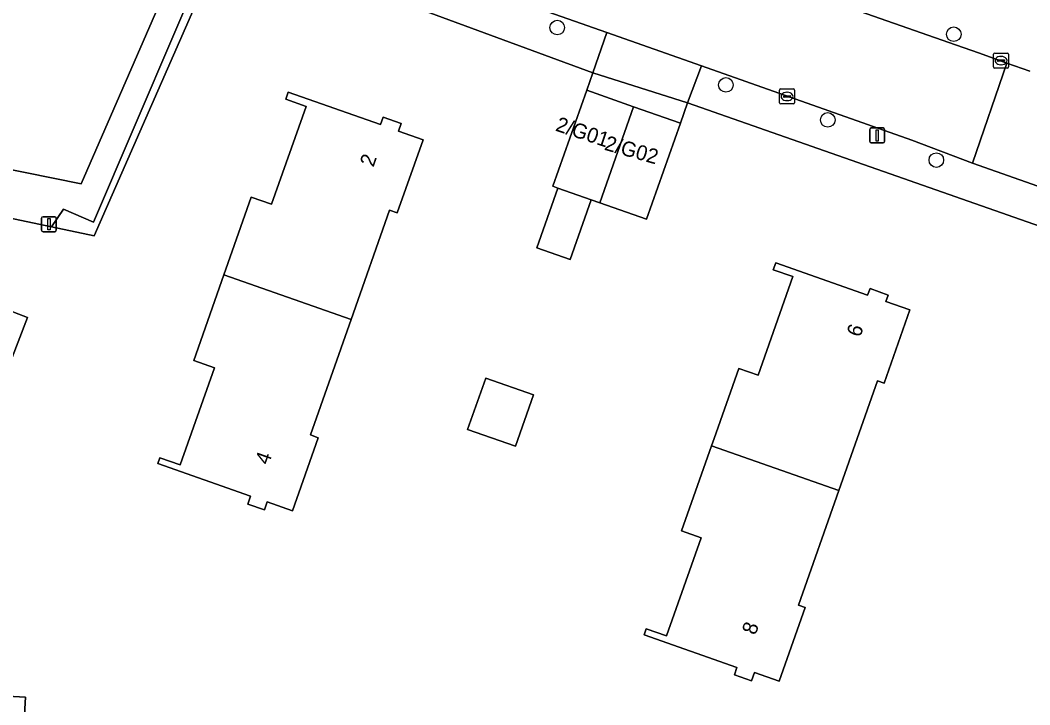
# Model space of a CAD drawing. Extents: x 163266 to 164362, y 381528 to 382286.
# Drawn here: x 163633.8 to 163701.5, y 381685.3 to 381731.2 of the extents above; entities that cross this region are included whole.
import ezdxf

# ---------------------------------------------------------------- set-up
doc = ezdxf.new("R2010")
doc.units = 0
for name, color, linetype in [('IMGEO_Boom', 7, 'Continuous'), ('IMGEO_Erf', 7, 'Continuous'), ('IMGEO_Groenvoorziening', 7, 'Continuous'), ('IMGEO_Kolk', 7, 'Continuous'), ('IMGEO_Lichtmast', 7, 'Continuous'), ('IMGEO_Pand', 7, 'Continuous'), ('IMGEO_Pand_nummerreeks', 7, 'Continuous'), ('IMGEO_Rijbaan_lokaal_open', 7, 'Continuous'), ('IMGEO_Voetpad_open', 7, 'Continuous')]:
    doc.layers.add(name, color=color, linetype=linetype)

msp = doc.modelspace()

# ---------------------------------------------------------------- linework, layer by layer
at = {"layer": 'IMGEO_Boom'}
for centre in [(163669.794, 381730.731), (163696.394, 381730.281), (163681.104, 381726.885), (163687.938, 381724.532), (163695.227, 381721.833)]:
    msp.add_circle(centre, 0.489, dxfattribs=at)
at = {"layer": 'IMGEO_Erf'}
msp.add_lwpolyline([(163745.303, 381694.051), (163749.229, 381692.724), (163751.277, 381698.534), (163751.759, 381699.934), (163743.762, 381702.736), (163737.338, 381704.902), (163711.131, 381714.194), (163704.828, 381716.464), (163678.538, 381725.673), (163678.063, 381724.312), (163675.791, 381717.865), (163672.646, 381718.973), (163672.074, 381719.175), (163670.661, 381715.164), (163668.428, 381715.95), (163669.842, 381719.961), (163669.501, 381720.081), (163671.774, 381726.529), (163672.171, 381727.69), (163647.526, 381736.802), (163638.731, 381716.751), (163635.855, 381717.357), (163618.556, 381721)], dxfattribs=at)
for points in [[(163672.171, 381727.69), (163671.774, 381726.529), (163674.918, 381725.42), (163678.063, 381724.312), (163678.538, 381725.673)], [(163649.037, 381698.745), (163649.224, 381699.275), (163642.995, 381701.47), (163643.132, 381701.857), (163644.501, 381701.374), (163646.796, 381707.886), (163645.403, 381708.377), (163647.43, 381714.128), (163649.27, 381719.35), (163650.632, 381718.87), (163652.946, 381725.436), (163651.578, 381725.918), (163651.747, 381726.398), (163657.927, 381724.22), (163658.106, 381724.727), (163659.331, 381724.295), (163659.149, 381723.779), (163660.793, 381723.2), (163659.061, 381718.285), (163658.546, 381718.466), (163655.962, 381711.134), (163653.232, 381703.385), (163653.762, 381703.198), (163652.034, 381698.296), (163650.342, 381698.892), (163650.152, 381698.352)], [(163681.848, 381687.774), (163675.623, 381689.968), (163675.769, 381690.381), (163677.132, 381689.9), (163679.45, 381696.479), (163678.139, 381696.942), (163680.149, 381702.647), (163680.322, 381703.137), (163681.984, 381707.852), (163683.267, 381707.4), (163685.597, 381714.012), (163684.288, 381714.473), (163684.449, 381714.931), (163690.617, 381712.758), (163690.775, 381713.206), (163691.99, 381712.777), (163691.838, 381712.345), (163693.449, 381711.778), (163691.715, 381706.856), (163691.274, 381707.011), (163688.681, 381699.654), (163685.969, 381691.958), (163686.429, 381691.796), (163684.688, 381686.856), (163683.016, 381687.445), (163682.815, 381686.875), (163681.673, 381687.277)], [(163625.049, 381706.105), (163627.966, 381713.682), (163634.25, 381711.263), (163631.333, 381703.686)], [(163663.783, 381703.753), (163664.997, 381707.199), (163668.206, 381706.074), (163666.992, 381702.628)], [(163630.045, 381672.483), (163622.26, 381672.933), (163622.545, 381677.925), (163622.841, 381683.109), (163623.419, 381683.076), (163623.607, 381686.383), (163628.458, 381686.107), (163634.117, 381685.785), (163633.89, 381681.792), (163633.729, 381678.958), (163630.424, 381679.148), (163630.301, 381676.99)]]:
    msp.add_lwpolyline(points, close=True, dxfattribs=at)
at = {"layer": 'IMGEO_Groenvoorziening'}
msp.add_lwpolyline([(163631.124, 381724.791), (163632.2, 381721.39), (163637.847, 381720.23), (163644.208, 381734.86)], dxfattribs=at)
at = {"layer": 'IMGEO_Kolk'}
for p, q in [((163699.065, 381728.087), (163699.065, 381728.939)), ((163699.14, 381729.013), (163699.992, 381729.013)), ((163699.367, 381728.556), (163699.765, 381728.556)), ((163699.553, 381728.793), (163699.578, 381728.793)), ((163700.066, 381728.939), (163700.066, 381728.087)), ((163699.992, 381728.013), (163699.14, 381728.013)), ((163699.324, 381728.507), (163699.324, 381728.519)), ((163699.762, 381728.47), (163699.364, 381728.47)), ((163699.576, 381728.233), (163699.551, 381728.233)), ((163699.808, 381728.519), (163699.808, 381728.507)), ((163684.71, 381725.682), (163684.71, 381726.534)), ((163684.785, 381726.608), (163685.637, 381726.608)), ((163685.711, 381726.534), (163685.711, 381725.682)), ((163684.969, 381726.102), (163684.969, 381726.114)), ((163685.407, 381726.065), (163685.009, 381726.065)), ((163685.012, 381726.151), (163685.41, 381726.151)), ((163685.221, 381725.828), (163685.196, 381725.828)), ((163685.198, 381726.388), (163685.223, 381726.388)), ((163685.453, 381726.114), (163685.453, 381726.102)), ((163685.637, 381725.608), (163684.785, 381725.608))]:
    msp.add_line(p, q, dxfattribs=at)
for points in [[(163699.065, 381728.087), (163699.065, 381728.939)], [(163699.14, 381729.013), (163699.992, 381729.013)], [(163700.066, 381728.939), (163700.066, 381728.087)], [(163699.992, 381728.013), (163699.14, 381728.013)], [(163684.71, 381725.682), (163684.71, 381726.534)], [(163684.785, 381726.608), (163685.637, 381726.608)], [(163685.711, 381726.534), (163685.711, 381725.682)], [(163685.637, 381725.608), (163684.785, 381725.608)]]:
    msp.add_lwpolyline(points, dxfattribs=at)
for centre, radius, start, end in [((163699.142, 381728.937), 0.0765, 91.55205, 178.44795), ((163699.142, 381728.937), 0.0765, 91.55205, 178.44795), ((163699.364, 381728.516), 0.0403, 85.87752, 175.75265), ((163699.769, 381728.518), 0.0386, 1.73085, 96.63898), ((163699.99, 381728.937), 0.0765, 1.55205, 88.44795), ((163699.99, 381728.937), 0.0765, 1.55205, 88.44795), ((163699.142, 381728.089), 0.0765, 181.55205, 268.44795), ((163699.142, 381728.089), 0.0765, 181.55205, 268.44795), ((163699.361, 381728.506), 0.0366, 178.93798, 274.71019), ((163699.765, 381728.513), 0.043, 264.86636, 352.45326), ((163699.99, 381728.089), 0.0765, 271.55205, 358.44795), ((163699.99, 381728.089), 0.0765, 271.55205, 358.44795), ((163684.787, 381726.532), 0.0765, 91.55205, 178.44795), ((163684.787, 381726.532), 0.0765, 91.55205, 178.44795), ((163685.635, 381726.532), 0.0765, 1.55205, 88.44795), ((163685.635, 381726.532), 0.0765, 1.55205, 88.44795), ((163685.009, 381726.111), 0.0403, 85.87752, 175.75265), ((163685.006, 381726.101), 0.0366, 178.93798, 274.71019), ((163685.41, 381726.108), 0.043, 264.86636, 352.45326), ((163685.414, 381726.113), 0.0386, 1.73085, 96.63898), ((163684.787, 381725.684), 0.0765, 181.55205, 268.44795), ((163684.787, 381725.684), 0.0765, 181.55205, 268.44795), ((163685.635, 381725.684), 0.0765, 271.55205, 358.44795), ((163685.635, 381725.684), 0.0765, 271.55205, 358.44795)]:
    msp.add_arc(centre, radius, start, end, dxfattribs=at)
for centre, major_axis, ratio, start_param, end_param in [((163699.552, 381728.513), (-0.387, 0.002), 0.722429, 4.712389, 7.853982), ((163699.577, 381728.513), (-0.39, 0.002), 0.717154, 1.570796, 4.712389), ((163685.197, 381726.108), (-0.387, 0.002), 0.722429, 4.712389, 7.853982), ((163685.222, 381726.108), (-0.39, 0.002), 0.717154, 1.570796, 4.712389)]:
    msp.add_ellipse(centre, major_axis=major_axis, ratio=ratio, start_param=start_param, end_param=end_param, dxfattribs=at)
at = {"layer": 'IMGEO_Lichtmast'}
for p, q in [((163690.761, 381723.089), (163690.761, 381723.889)), ((163690.761, 381723.889), (163690.761, 381723.089)), ((163690.861, 381723.989), (163691.651, 381723.989)), ((163691.651, 381723.989), (163690.861, 381723.989)), ((163691.751, 381723.889), (163691.751, 381723.089)), ((163691.751, 381723.089), (163691.751, 381723.889)), ((163691.651, 381722.989), (163690.861, 381722.989)), ((163690.861, 381722.989), (163691.651, 381722.989)), ((163635.196, 381717.129), (163635.196, 381717.929)), ((163635.196, 381717.929), (163635.196, 381717.129)), ((163635.296, 381718.029), (163636.086, 381718.029)), ((163636.086, 381718.029), (163635.296, 381718.029)), ((163636.186, 381717.929), (163636.186, 381717.129)), ((163636.186, 381717.129), (163636.186, 381717.929)), ((163636.086, 381717.029), (163635.296, 381717.029)), ((163635.296, 381717.029), (163636.086, 381717.029))]:
    msp.add_line(p, q, dxfattribs=at)
for points in [[(163691.181, 381723.864), (163691.331, 381723.864), (163691.331, 381723.114), (163691.181, 381723.114), (163691.181, 381723.864)], [(163635.616, 381717.904), (163635.766, 381717.904), (163635.766, 381717.154), (163635.616, 381717.154), (163635.616, 381717.904)]]:
    msp.add_lwpolyline(points, dxfattribs=at)
for centre, start, end in [((163690.861, 381723.889), 90, 180), ((163690.861, 381723.889), 90, 180), ((163691.651, 381723.889), 0, 90), ((163691.651, 381723.889), 360, 90), ((163690.861, 381723.089), 180, 270), ((163690.861, 381723.089), 180, 270), ((163691.651, 381723.089), 270, 0), ((163691.651, 381723.089), 270, 0), ((163635.296, 381717.929), 90, 180), ((163635.296, 381717.929), 90, 180), ((163636.086, 381717.929), 0, 90), ((163636.086, 381717.929), 360, 90), ((163635.296, 381717.129), 180, 270), ((163635.296, 381717.129), 180, 270), ((163636.086, 381717.129), 270, 0), ((163636.086, 381717.129), 270, 0)]:
    msp.add_arc(centre, 0.1, start, end, dxfattribs=at)
at = {"layer": 'IMGEO_Pand'}
for points in [[(163674.918, 381725.42), (163671.774, 381726.529), (163669.501, 381720.081), (163669.842, 381719.961), (163672.074, 381719.175), (163672.646, 381718.973)], [(163647.43, 381714.128), (163655.962, 381711.134), (163658.546, 381718.466), (163659.061, 381718.285), (163660.793, 381723.2), (163659.149, 381723.779), (163659.331, 381724.295), (163658.106, 381724.727), (163657.927, 381724.22), (163651.747, 381726.398), (163651.578, 381725.918), (163652.946, 381725.436), (163650.632, 381718.87), (163649.27, 381719.35)], [(163675.791, 381717.865), (163678.063, 381724.312), (163674.918, 381725.42), (163672.646, 381718.973)], [(163672.074, 381719.175), (163669.842, 381719.961), (163668.428, 381715.95), (163670.661, 381715.164)], [(163680.149, 381702.647), (163688.681, 381699.654), (163691.274, 381707.011), (163691.715, 381706.856), (163693.449, 381711.778), (163691.838, 381712.345), (163691.99, 381712.777), (163690.775, 381713.206), (163690.617, 381712.758), (163684.449, 381714.931), (163684.288, 381714.473), (163685.597, 381714.012), (163683.267, 381707.4), (163681.984, 381707.852), (163680.322, 381703.137)], [(163634.25, 381711.263), (163627.966, 381713.682), (163625.049, 381706.105), (163631.333, 381703.686)], [(163647.43, 381714.128), (163645.403, 381708.377), (163646.796, 381707.886), (163644.501, 381701.374), (163643.132, 381701.857), (163642.995, 381701.47), (163649.224, 381699.275), (163649.037, 381698.745), (163650.152, 381698.352), (163650.342, 381698.892), (163652.034, 381698.296), (163653.762, 381703.198), (163653.232, 381703.385), (163655.962, 381711.134)], [(163663.783, 381703.753), (163666.992, 381702.628), (163668.206, 381706.074), (163664.997, 381707.199)], [(163680.149, 381702.647), (163678.139, 381696.942), (163679.45, 381696.479), (163677.132, 381689.9), (163675.769, 381690.381), (163675.623, 381689.968), (163681.848, 381687.774), (163681.673, 381687.277), (163682.815, 381686.875), (163683.016, 381687.445), (163684.688, 381686.856), (163686.429, 381691.796), (163685.969, 381691.958), (163688.681, 381699.654)], [(163633.89, 381681.792), (163634.117, 381685.785), (163628.458, 381686.107), (163623.607, 381686.383), (163623.419, 381683.076), (163622.841, 381683.109), (163622.545, 381677.925), (163622.26, 381672.933), (163630.045, 381672.483), (163630.301, 381676.99), (163630.424, 381679.148), (163633.729, 381678.958)]]:
    msp.add_lwpolyline(points, close=True, dxfattribs=at)
at = {"layer": 'IMGEO_Rijbaan_lokaal_open'}
msp.add_lwpolyline([(163658.899, 381742.752), (163654.429, 381744.322), (163652.132, 381737.784), (163673.109, 381730.393), (163679.468, 381728.152), (163693.576, 381723.182), (163697.64, 381721.621), (163699.958, 381728.351), (163698.123, 381729.013), (163696.505, 381729.58)], close=True, dxfattribs=at)
msp.add_lwpolyline([(163701.495, 381727.796), (163699.958, 381728.351), (163697.64, 381721.621), (163705.584, 381718.826), (163712, 381716.568), (163727.274, 381711.194), (163729.531, 381717.818), (163728.582, 381718.152)], dxfattribs=at)
at = {"layer": 'IMGEO_Voetpad_open'}
for points in [[(163681.177, 381738.741), (163679.939, 381739.182), (163679.863, 381738.968), (163672.598, 381741.556), (163672.674, 381741.768), (163655.729, 381747.8), (163654.429, 381744.322), (163658.899, 381742.752), (163696.505, 381729.58), (163698.123, 381729.013), (163699.958, 381728.351), (163701.495, 381727.796)], [(163618.556, 381721), (163635.855, 381717.357), (163636.66, 381718.535), (163638.684, 381717.669), (163646.93, 381736.976), (163647.539, 381739.402), (163645.29, 381740.061), (163643.927, 381740.549), (163642.897, 381740.905)], [(163644.208, 381734.86), (163637.847, 381720.23), (163632.2, 381721.39), (163631.124, 381724.791)]]:
    msp.add_lwpolyline(points, dxfattribs=at)
for points in [[(163652.132, 381737.784), (163650.44, 381738.38), (163648.445, 381739.083), (163647.846, 381739.294), (163647.539, 381739.402), (163646.93, 381736.976), (163647.526, 381736.802), (163672.171, 381727.69), (163673.109, 381730.393)], [(163647.526, 381736.802), (163646.93, 381736.976), (163638.684, 381717.669), (163636.66, 381718.535), (163635.855, 381717.357), (163638.731, 381716.751)], [(163678.538, 381725.673), (163679.468, 381728.152), (163673.109, 381730.393), (163672.171, 381727.69)], [(163693.576, 381723.182), (163679.468, 381728.152), (163678.538, 381725.673), (163704.828, 381716.464), (163705.584, 381718.826), (163697.64, 381721.621)]]:
    msp.add_lwpolyline(points, close=True, dxfattribs=at)

# ---------------------------------------------------------------- texts
at = {"layer": 'IMGEO_Pand_nummerreeks'}
for s, rotation, p in [('2/G01', 341.65962, (163669.617, 381723.824)), ('2/G02', 344.10569, (163672.898, 381722.538)), ('2', 70.58802, (163657.458, 381721.318)), ('6', 70.59285, (163690.114, 381709.895)), ('4', 70.58198, (163650.43, 381701.325)), ('8', 70.58606, (163683.091, 381689.907))]:
    msp.add_text(s, height=1, rotation=rotation, dxfattribs=at).set_placement(p)

doc.saveas('drawing.dxf')
